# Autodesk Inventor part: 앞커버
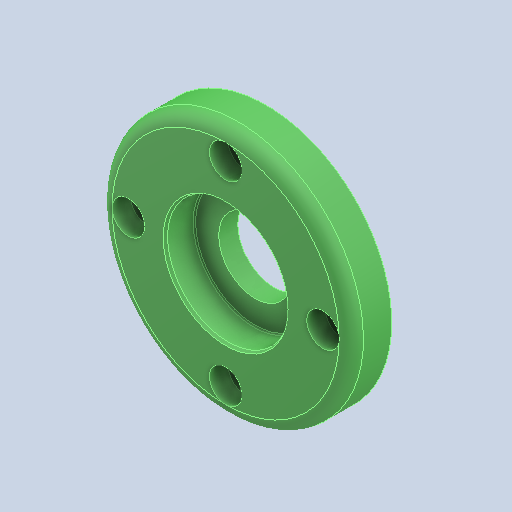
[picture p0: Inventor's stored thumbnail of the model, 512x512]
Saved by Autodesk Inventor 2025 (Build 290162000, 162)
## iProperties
Created: 2025-08
Part Number: 앞커버
Material: 알루미늄 6061
Document SubType Name: Modeling
Designer: infra017
Density: 2.71 g/cm^3
Appearance: 기본값
Author: jhkim
Sending System: Autodesk Inventor 2026
Preprocessor: ST-DEVELOPER v20.1
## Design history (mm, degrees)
feature "솔리드1"
node "솔리드2"
